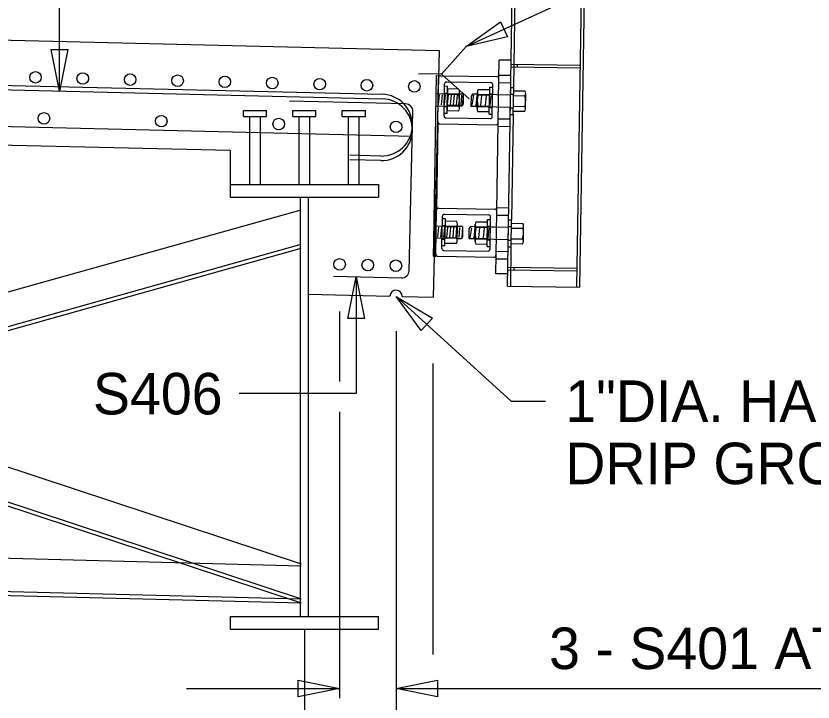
# Model space of a CAD drawing. Extents: x -86 to 68, y -5 to 62.
# Drawn here: x 51.65 to 57.02, y 22.23 to 26.86 of the extents above; entities that cross this region are included whole.
import ezdxf

# ---------------------------------------------------------------- set-up
doc = ezdxf.new("R2010")
doc.units = 0
for name, color, linetype in [('BR_P_Dia_Reinforcing', 7, 'Continuous'), ('BR_P_Gen_Text', 7, 'Continuous'), ('BR_P_Gen_Waterproofing', 7, 'Continuous'), ('BR_P_Rail_Hidden', 7, 'Continuous'), ('BR_P_Rail_Object', 7, 'Continuous'), ('BR_P_Slab_Object', 7, 'Continuous'), ('BR_P_Slab_Reinforcing', 7, 'Continuous'), ('BR_X_Beam_Centerline', 7, 'Continuous'), ('BR_X_Beam_Object', 7, 'Continuous'), ('TX_P_1', 7, 'Continuous'), ('TX_P_5', 7, 'Continuous')]:
    doc.layers.add(name, color=color, linetype=linetype)

msp = doc.modelspace()

# ---------------------------------------------------------------- linework, layer by layer
at = {"layer": 'BR_P_Dia_Reinforcing'}
for centre in [(52.4157, 26.4302), (53.374, 26.4072), (54.3323, 26.3842), (51.834, 26.1685), (52.6257, 26.1495), (53.4174, 26.1305), (54.209, 26.1115), (53.8285, 25.1837), (54.0182, 25.1791), (54.208, 25.1746)]:
    msp.add_circle(centre, 0.039, dxfattribs=at)
at = {"layer": 'BR_P_Gen_Text'}
for points in [[(54.913, 26.8211), (54.9599, 26.7194), (54.6822, 26.653)], [(51.8823, 26.6326), (51.9943, 26.6326), (51.9383, 26.3526)], [(53.9956, 24.8194), (53.8836, 24.8194), (53.9396, 25.0994)], [(54.4538, 24.8208), (54.3785, 24.738), (54.2091, 24.9679)], [(53.5485, 22.2651), (53.5485, 22.3771), (53.8285, 22.3211)], [(54.489, 22.3771), (54.489, 22.2651), (54.209, 22.3211)]]:
    msp.add_lwpolyline(points, close=True, dxfattribs=at)
at = {"layer": 'BR_P_Gen_Waterproofing'}
for q in [(54.6822, 26.653), (54.3603, 26.4694), (54.7012, 26.2999)]:
    msp.add_line((54.5152, 26.4669), q, dxfattribs=at)
at = {"layer": 'BR_P_Rail_Hidden'}
for p, q in [((54.9022, 26.4367), (54.9043, 26.562)), ((54.9855, 26.5607), (54.9043, 26.562)), ((54.9026, 26.4604), (54.9839, 26.4591)), ((54.9018, 26.4096), (54.9831, 26.4083)), ((54.535, 26.3393), (54.5553, 26.339)), ((54.7574, 26.3316), (54.8861, 26.3295)), ((54.7812, 26.2558), (54.7881, 26.3234)), ((54.8128, 26.2553), (54.8197, 26.3229)), ((54.8397, 26.3344), (54.86, 26.3341)), ((54.8444, 26.2548), (54.8513, 26.3224)), ((54.8586, 26.2469), (54.8599, 26.3299)), ((54.8861, 26.3295), (54.9818, 26.328)), ((54.9818, 26.3322), (55.0021, 26.3318)), ((54.5336, 26.2479), (54.5539, 26.2476)), ((54.7561, 26.2485), (54.8848, 26.2465)), ((54.8382, 26.243), (54.8585, 26.2427)), ((54.8848, 26.2465), (54.9804, 26.245)), ((54.9804, 26.2408), (55.0007, 26.2404)), ((54.8879, 25.5431), (54.8975, 26.1388)), ((54.8979, 26.1659), (54.9792, 26.1646)), ((54.8971, 26.1151), (54.9783, 26.1138)), ((54.8883, 25.5668), (54.9696, 25.5655)), ((54.8875, 25.516), (54.9688, 25.5147)), ((54.5207, 25.4457), (54.541, 25.4454)), ((54.7431, 25.4379), (54.8719, 25.4359)), ((54.8254, 25.4408), (54.8457, 25.4405)), ((54.8443, 25.3533), (54.8456, 25.4363)), ((54.8719, 25.4359), (54.9675, 25.4343)), ((54.9675, 25.4385), (54.9878, 25.4382)), ((54.7669, 25.3622), (54.7738, 25.4298)), ((54.7985, 25.3617), (54.8054, 25.4293)), ((54.8301, 25.3611), (54.837, 25.4288)), ((54.5193, 25.3543), (54.5396, 25.354)), ((54.7418, 25.3549), (54.8705, 25.3529)), ((54.8239, 25.3494), (54.8442, 25.3491)), ((54.8705, 25.3529), (54.9661, 25.3513)), ((54.9661, 25.3471), (54.9864, 25.3468)), ((54.8836, 25.2723), (54.9649, 25.271)), ((54.8812, 25.12), (54.8832, 25.2452)), ((54.8828, 25.2215), (54.964, 25.2202)), ((54.9624, 25.1187), (54.8812, 25.12))]:
    msp.add_line(p, q, dxfattribs=at)
at = {"layer": 'BR_P_Rail_Object'}
for p, q in [((55.0037, 26.3775), (55.0524, 29.424)), ((55.4486, 25.0296), (55.5187, 29.4165)), ((55.4274, 25.0299), (55.4885, 28.8482)), ((54.9611, 25.0374), (55.0023, 27.6134)), ((55.0257, 26.5346), (55.0254, 26.5143)), ((54.4632, 25.3437), (54.481, 26.457)), ((54.481, 26.457), (54.4963, 26.4567)), ((54.4963, 26.4567), (54.496, 26.4432)), ((54.5098, 26.4565), (54.8889, 26.4505)), ((54.4913, 26.1451), (54.496, 26.4432)), ((54.5326, 26.1853), (54.536, 26.4019)), ((54.5498, 26.4153), (54.8477, 26.4105)), ((54.8975, 26.1388), (54.9022, 26.4367)), ((54.5328, 26.2022), (54.5357, 26.385)), ((54.5561, 26.3847), (54.5357, 26.385)), ((54.5531, 26.2019), (54.5561, 26.3847)), ((54.5558, 26.3678), (54.5534, 26.2188)), ((54.6326, 26.3665), (54.5558, 26.3678)), ((54.6359, 26.2361), (54.6377, 26.3478)), ((54.7558, 26.2342), (54.7576, 26.3459)), ((54.7633, 26.3644), (54.8401, 26.3632)), ((54.8375, 26.1973), (54.8404, 26.3801)), ((54.8404, 26.3801), (54.8607, 26.3798)), ((54.8578, 26.197), (54.8607, 26.3798)), ((54.8607, 26.3798), (54.861, 26.3967)), ((54.9796, 26.1951), (54.9826, 26.3779)), ((54.9826, 26.3779), (55.0029, 26.3775)), ((55, 26.1947), (55.0029, 26.3775)), ((55.0025, 26.3547), (55.0787, 26.3535)), ((54.6375, 26.3326), (54.4791, 26.3351)), ((54.4989, 26.3281), (54.4935, 26.2604)), ((54.5192, 26.3277), (54.5139, 26.2601)), ((54.5395, 26.3274), (54.5342, 26.2597)), ((54.5598, 26.3271), (54.5545, 26.2594)), ((54.632, 26.3293), (54.5552, 26.3305)), ((54.5801, 26.3268), (54.5748, 26.2591)), ((54.6004, 26.3264), (54.5951, 26.2588)), ((54.6207, 26.3261), (54.6154, 26.2584)), ((54.6619, 26.3322), (54.6375, 26.3326)), ((54.6512, 26.3256), (54.6459, 26.258)), ((54.6619, 26.3322), (54.6555, 26.251)), ((54.6619, 26.3322), (54.6608, 26.2642)), ((54.7164, 26.2492), (54.7175, 26.3201)), ((54.7257, 26.3321), (54.7175, 26.3201)), ((54.7234, 26.2567), (54.7339, 26.3243)), ((54.7574, 26.3316), (54.7257, 26.3321)), ((54.7496, 26.2563), (54.7565, 26.3239)), ((54.7627, 26.3272), (54.8395, 26.326)), ((55.002, 26.3222), (55.0781, 26.321)), ((55.0821, 26.2325), (55.0838, 26.3372)), ((54.4778, 26.2539), (54.6362, 26.2514)), ((54.6308, 26.2548), (54.554, 26.2561)), ((54.6555, 26.251), (54.6362, 26.2514)), ((54.6608, 26.2642), (54.6555, 26.251)), ((54.7561, 26.2485), (54.7164, 26.2492)), ((54.7615, 26.2527), (54.8383, 26.2515)), ((55.0008, 26.25), (55.077, 26.2488)), ((54.5531, 26.2019), (54.5328, 26.2022)), ((54.6302, 26.2176), (54.5534, 26.2188)), ((54.7609, 26.2155), (54.8377, 26.2143)), ((54.8375, 26.1973), (54.8578, 26.197)), ((54.8575, 26.1801), (54.8578, 26.197)), ((54.9796, 26.1951), (55, 26.1947)), ((54.9894, 25.4839), (55.0008, 26.1947)), ((55.0003, 26.2176), (55.0765, 26.2163)), ((54.4913, 26.1453), (54.4818, 25.5496)), ((54.5046, 26.1316), (54.8837, 26.1255)), ((54.5459, 26.1715), (54.8438, 26.1668)), ((54.477, 25.2517), (54.4818, 25.5496)), ((54.4955, 25.5629), (54.8746, 25.5568)), ((54.8832, 25.2452), (54.8879, 25.5431)), ((54.5185, 25.3086), (54.5215, 25.4914)), ((54.5215, 25.4914), (54.5217, 25.5083)), ((54.5418, 25.4911), (54.5215, 25.4914)), ((54.5355, 25.5216), (54.8334, 25.5169)), ((54.5388, 25.3083), (54.5418, 25.4911)), ((54.8232, 25.3037), (54.8261, 25.4865)), ((54.8261, 25.4865), (54.8464, 25.4862)), ((54.8435, 25.3034), (54.8464, 25.4862)), ((54.8464, 25.4862), (54.8467, 25.5031)), ((54.9653, 25.3014), (54.9683, 25.4842)), ((54.9683, 25.4842), (54.9886, 25.4839)), ((54.9857, 25.3011), (54.9886, 25.4839)), ((54.6232, 25.439), (54.4648, 25.4415)), ((54.4744, 25.4346), (54.4691, 25.3669)), ((54.4947, 25.4343), (54.4894, 25.3666)), ((54.515, 25.4339), (54.5097, 25.3663)), ((54.5353, 25.4336), (54.53, 25.366)), ((54.6177, 25.4357), (54.5409, 25.4369)), ((54.6183, 25.4729), (54.5415, 25.4741)), ((54.5557, 25.4333), (54.5503, 25.3656)), ((54.576, 25.433), (54.5706, 25.3653)), ((54.5963, 25.4326), (54.591, 25.365)), ((54.6166, 25.4323), (54.6113, 25.3647)), ((54.6216, 25.3425), (54.6234, 25.4542)), ((54.6577, 25.4384), (54.6232, 25.439)), ((54.6369, 25.432), (54.6316, 25.3643)), ((54.6572, 25.4317), (54.6519, 25.364)), ((54.6577, 25.4384), (54.6566, 25.3704)), ((54.7114, 25.4384), (54.7032, 25.4265)), ((54.7091, 25.3631), (54.7196, 25.4307)), ((54.7431, 25.4379), (54.7114, 25.4384)), ((54.7353, 25.3627), (54.7422, 25.4303)), ((54.7415, 25.3406), (54.7433, 25.4523)), ((54.7484, 25.4336), (54.8252, 25.4323)), ((54.749, 25.4708), (54.8258, 25.4696)), ((54.9882, 25.4611), (55.0644, 25.4599)), ((55.0678, 25.3389), (55.0695, 25.4435)), ((54.7021, 25.3555), (54.7032, 25.4265)), ((54.9877, 25.4286), (55.0638, 25.4274)), ((54.4615, 25.2384), (54.4632, 25.3437)), ((54.6219, 25.3577), (54.4635, 25.3603)), ((54.6159, 25.324), (54.5391, 25.3252)), ((54.6165, 25.3612), (54.5397, 25.3624)), ((54.6219, 25.3577), (54.6514, 25.3573)), ((54.6566, 25.3704), (54.6514, 25.3573)), ((54.7418, 25.3549), (54.7021, 25.3555)), ((54.7472, 25.3591), (54.824, 25.3579)), ((54.986, 25.3239), (55.0622, 25.3227)), ((54.9865, 25.3564), (55.0627, 25.3552)), ((54.5183, 25.2917), (54.5185, 25.3086)), ((54.5388, 25.3083), (54.5185, 25.3086)), ((54.5316, 25.2779), (54.8295, 25.2731)), ((54.7466, 25.3219), (54.8234, 25.3206)), ((54.8232, 25.3037), (54.8435, 25.3034)), ((54.8432, 25.2865), (54.8435, 25.3034)), ((54.9653, 25.3014), (54.9857, 25.3011)), ((54.9822, 25.0371), (54.9865, 25.3011)), ((54.4615, 25.2384), (54.4768, 25.2382)), ((54.4768, 25.2382), (54.477, 25.2517)), ((54.4903, 25.2379), (54.8694, 25.2319)), ((55.0038, 25.1637), (55.0034, 25.1434)), ((54.9611, 25.0374), (55.4486, 25.0296))]:
    msp.add_line(p, q, dxfattribs=at)
for points in [[(55.4503, 26.5075), (54.9848, 26.515), (54.9851, 26.5353), (55.4506, 26.5278)], [(55.4283, 25.1366), (54.9628, 25.144), (54.9631, 25.1643), (55.4287, 25.1569)]]:
    msp.add_lwpolyline(points, close=True, dxfattribs=at)
for centre, radius, start, end in [((54.5096, 26.443), 0.0135, 89.0833, 179.0833), ((54.5496, 26.4017), 0.0135, 89.0833, 179.0833), ((54.8474, 26.397), 0.0135, 359.0833, 89.0833), ((54.8887, 26.4369), 0.0135, 359.0833, 89.0833), ((54.603, 26.3484), 0.0347, 326.643, 31.5237), ((54.7923, 26.3454), 0.0347, 146.643, 211.5237), ((55.0567, 26.3376), 0.0271, 322.2134, 35.9532), ((54.5061, 26.2941), 0.1307, 342.5316, 15.6351), ((54.8874, 26.288), 0.1307, 162.5316, 195.6351), ((54.96, 26.2868), 0.123, 342.0176, 16.1491), ((54.6012, 26.2367), 0.0347, 326.643, 31.5237), ((54.7905, 26.2337), 0.0347, 146.643, 211.5237), ((55.0551, 26.2329), 0.0271, 322.2134, 35.9532), ((54.5461, 26.1851), 0.0135, 179.0833, 269.0833), ((54.5048, 26.1451), 0.0135, 179.0833, 269.0833), ((54.844, 26.1803), 0.0135, 269.0833, 359.0833), ((54.8839, 26.139), 0.0135, 269.0833, 359.0833), ((54.4953, 25.5494), 0.0135, 89.0833, 179.0833), ((54.8744, 25.5433), 0.0135, 359.0833, 89.0833), ((54.5353, 25.5081), 0.0135, 89.0833, 179.0833), ((54.8331, 25.5033), 0.0135, 359.0833, 89.0833), ((54.4918, 25.4004), 0.1307, 342.5316, 15.6351), ((54.5887, 25.4548), 0.0347, 326.643, 31.5237), ((54.8731, 25.3943), 0.1307, 162.5316, 195.6351), ((54.778, 25.4517), 0.0347, 146.643, 211.5237), ((55.0424, 25.444), 0.0271, 322.2134, 35.9532), ((54.9457, 25.3932), 0.123, 342.0176, 16.1491), ((54.5869, 25.343), 0.0347, 326.643, 31.5237), ((54.7762, 25.34), 0.0347, 146.643, 211.5237), ((55.0408, 25.3393), 0.0271, 322.2134, 35.9532), ((54.5318, 25.2914), 0.0135, 179.0833, 269.0833), ((54.8297, 25.2867), 0.0135, 269.0833, 359.0833), ((54.4905, 25.2515), 0.0135, 179.0833, 269.0833), ((54.8696, 25.2454), 0.0135, 269.0833, 359.0833)]:
    msp.add_arc(centre, radius, start, end, dxfattribs=at)
at = {"layer": 'BR_P_Slab_Object'}
for p, q in [((12.499, 27.6356), (54.499, 26.6276)), ((54.499, 26.6276), (54.459, 24.9619)), ((46.221, 26.1179), (53.091, 25.9531)), ((53.091, 25.9531), (53.091, 25.7227)), ((53.6181, 24.9821), (54.1674, 24.9689)), ((54.2507, 24.9669), (54.459, 24.9619))]:
    msp.add_line(p, q, dxfattribs=at)
msp.add_arc((54.2091, 24.9679), 0.0417, 358.6252, 178.6252, dxfattribs=at)
at = {"layer": 'BR_P_Slab_Reinforcing'}
for p, q in [((34.2083, 26.8089), (54.1159, 26.3311)), ((34.0833, 26.5343), (54.3184, 26.0486)), ((49.091, 26.4209), (54.1159, 26.3003)), ((54.2736, 26.2658), (53.4905, 26.2846)), ((54.2966, 25.1408), (54.3224, 26.2146)), ((54.1059, 25.9145), (53.8976, 25.9195)), ((54.1059, 25.8838), (53.8976, 25.8888)), ((53.7877, 25.103), (54.2454, 25.0921))]:
    msp.add_line(p, q, dxfattribs=at)
for centre in [(51.7772, 26.4455), (52.0958, 26.4379), (52.7356, 26.4225), (53.0541, 26.4149), (53.6939, 26.3995), (54.0124, 26.3919)]:
    msp.add_circle(centre, 0.039, dxfattribs=at)
for centre, radius, start, end in [((54.1109, 26.1228), 0.2083, 268.6252, 88.6252), ((54.1109, 26.0921), 0.2083, 268.6252, 88.6252), ((54.2724, 26.2158), 0.05, 358.6252, 88.6252), ((54.2466, 25.142), 0.05, 268.6252, 358.6252)]:
    msp.add_arc(centre, radius, start, end, dxfattribs=at)
at = {"layer": 'BR_X_Beam_Centerline'}
msp.add_line((53.591, 22.7219), (53.591, 15.0334), dxfattribs=at)
at = {"layer": 'BR_X_Beam_Object'}
for p, q in [((45.7481, 25.7474), (53.5689, 23.1632)), ((53.091, 25.7227), (54.091, 25.7227)), ((53.091, 25.7227), (53.091, 25.6377)), ((54.091, 25.7227), (54.091, 25.6377)), ((53.091, 25.6377), (54.091, 25.6377)), ((53.5639, 22.8069), (53.5639, 25.6377)), ((53.6181, 22.8069), (53.6181, 25.6377)), ((45.7481, 23.3595), (53.5689, 25.5515)), ((45.7481, 25.5115), (53.5689, 22.9273)), ((45.7481, 25.4841), (53.5689, 22.8999)), ((45.7481, 23.1269), (53.5689, 25.3188)), ((45.7481, 23.0999), (53.5689, 25.2918)), ((45.7481, 23.35), (53.5689, 23.15)), ((45.7481, 23.1259), (53.5689, 22.9259)), ((45.7481, 23.0999), (53.5689, 22.8999)), ((53.091, 22.8069), (54.091, 22.8069)), ((53.091, 22.8069), (53.091, 22.7219)), ((54.091, 22.7219), (54.091, 22.8069)), ((53.091, 22.7219), (54.091, 22.7219))]:
    msp.add_line(p, q, dxfattribs=at)
at = {"layer": 'TX_P_1'}
for p, q in [((51.9383, 26.3526), (51.9383, 28.5418)), ((54.6822, 26.653), (56.7455, 27.6046)), ((53.9396, 25.0994), (53.9396, 24.3112)), ((54.2091, 24.9679), (54.9862, 24.2605)), ((53.8285, 24.8654), (53.8285, 24.3927)), ((54.209, 24.734), (54.209, 18.8957)), ((54.459, 22.551), (54.459, 24.5138)), ((53.9396, 24.3112), (53.1514, 24.3112)), ((54.9862, 24.2605), (55.2173, 24.2605)), ((53.8285, 24.1884), (53.8285, 22.2562)), ((52.7966, 22.3211), (53.8285, 22.3211)), ((54.209, 22.3211), (57.9168, 22.3211))]:
    msp.add_line(p, q, dxfattribs=at)
at = {"layer": 'TX_P_5'}
for p, q in [((53.1797, 26.2227), (53.3357, 26.2227)), ((53.1797, 26.1807), (53.1797, 26.2227)), ((53.3357, 26.1807), (53.3357, 26.2227)), ((53.513, 26.2227), (53.669, 26.2227)), ((53.513, 26.1807), (53.513, 26.2227)), ((53.669, 26.1807), (53.669, 26.2227)), ((53.8463, 26.2227), (54.0023, 26.2227)), ((53.8463, 26.1807), (53.8463, 26.2227)), ((54.0023, 26.1807), (54.0023, 26.2227)), ((53.1797, 26.1807), (53.3357, 26.1807)), ((53.2217, 25.7227), (53.2217, 26.1807)), ((53.2937, 25.7227), (53.2937, 26.1807)), ((53.513, 26.1807), (53.669, 26.1807)), ((53.555, 25.7227), (53.555, 26.1807)), ((53.627, 25.7227), (53.627, 26.1807)), ((53.8463, 26.1807), (54.0023, 26.1807)), ((53.8883, 25.7227), (53.8883, 26.1807)), ((53.9603, 25.7227), (53.9603, 26.1807))]:
    msp.add_line(p, q, dxfattribs=at)

# ---------------------------------------------------------------- texts
at = {"layer": 'TX_P_1'}
for s, p in [('S406', (52.1646, 24.1712)), ('1"DIA. HALF ROUND', (55.3504, 24.1205)), ('DRIP GROOVE (TYP)', (55.3504, 23.7005)), ('3 - S401 AT', (55.2411, 22.4531))]:
    msp.add_text(s, height=0.28, dxfattribs=at).set_placement(p)

doc.saveas('drawing.dxf')
